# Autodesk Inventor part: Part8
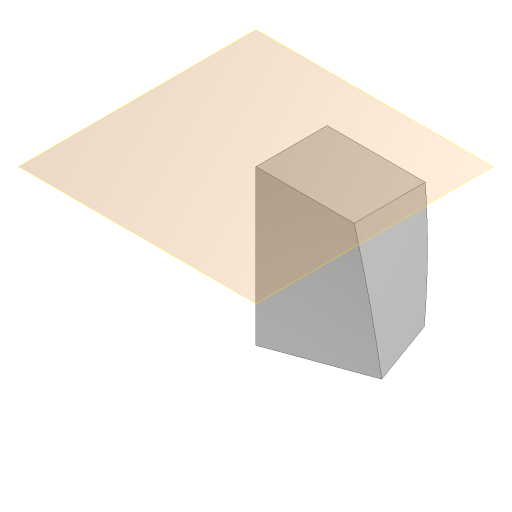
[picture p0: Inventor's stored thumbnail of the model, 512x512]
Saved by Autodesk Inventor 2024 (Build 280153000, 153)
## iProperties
Created: 2015-07
Part Number: Part8
Material: Generic
Document SubType Name: Modeling
Designer: Sandeep
Density: 1 g/cm^3
Appearance: Default
Author: Sandeep
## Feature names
1. Sweep1
## Parameters: d0 = 0, d1 = -20 deg
